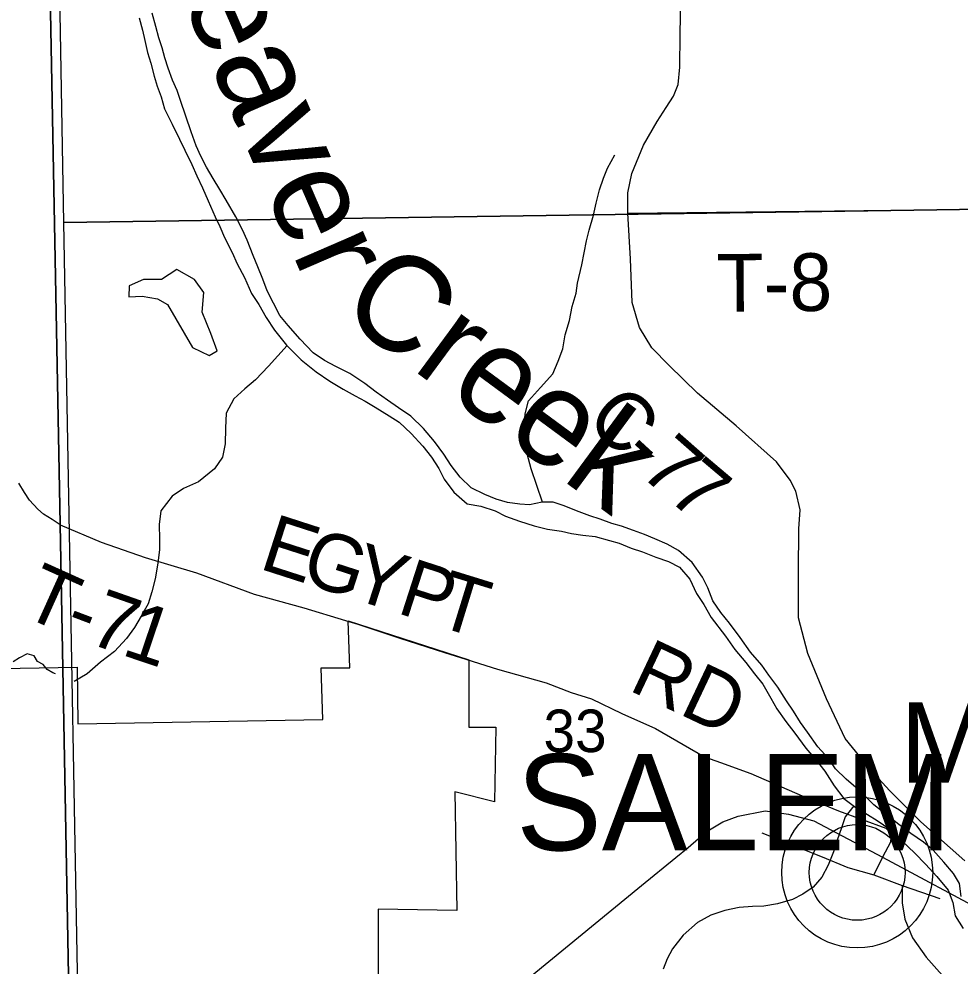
# Model space of a CAD drawing. Extents: x 0 to 34, y 0 to 22.
# Drawn here: x 7.33 to 8.257, y 17.555 to 18.489 of the extents above; entities that cross this region are included whole.
import ezdxf

# ---------------------------------------------------------------- set-up
doc = ezdxf.new("R2010")
doc.units = 0
for name, color, linetype in [('GM_X_Corporation', 7, 'Continuous'), ('GM_X_Corporation_Text', 7, 'Continuous'), ('GM_X_County_Road', 7, 'Continuous'), ('GM_X_County_Road_Text', 7, 'Continuous'), ('GM_X_Minor_Lake', 7, 'Continuous'), ('GM_X_Minor_River', 7, 'Continuous'), ('GM_X_Minor_River_Text', 7, 'Continuous'), ('GM_X_Rail_Line', 7, 'Continuous'), ('GM_X_Section', 7, 'Continuous'), ('GM_X_Section_Text', 7, 'Continuous'), ('GM_X_State_Route', 7, 'Continuous'), ('GM_X_Township', 7, 'Continuous'), ('GM_X_Township_Road', 7, 'Continuous'), ('GM_X_Township_Road_Text', 7, 'Continuous'), ('GM_X_Unincorporated', 7, 'Continuous'), ('GM_X_Unincorporated_Location', 7, 'Continuous'), ('GM_X_Unincorporated_Text', 7, 'Continuous'), ('SH_Cut_Line', 7, 'Continuous')]:
    doc.layers.add(name, color=color, linetype=linetype)

msp = doc.modelspace()

# ---------------------------------------------------------------- linework, layer by layer
at = {"layer": 'GM_X_Corporation'}
msp.add_lwpolyline([(7.08777, 17.84487), (7.38675, 17.85009), (7.38759, 17.79415), (7.62904, 17.79837), (7.62726, 17.84947), (7.65548, 17.84947), (7.65386, 17.89577), (7.77292, 17.85735), (7.77292, 17.79073), (7.79944, 17.79073), (7.79816, 17.71744), (7.75902, 17.72721), (7.76106, 17.61018), (7.68361, 17.61153), (7.68361, 17.42295)], dxfattribs=at)
at = {"layer": 'GM_X_County_Road'}
for points in [[(7.93338, 18.33639), (7.94497, 18.36437), (7.95857, 18.38746), (7.96741, 18.40133), (7.97441, 18.41249), (7.97911, 18.424), (7.98066, 18.44113), (7.98114, 18.47345), (7.98191, 18.52821), (7.982, 18.63427), (7.97887, 18.74901), (7.97794, 18.79423), (7.96834, 18.81722), (7.93809, 18.901), (7.91191, 18.97155), (7.89774, 19.01309), (7.88162, 19.05724), (7.86677, 19.09495), (7.85711, 19.12061), (7.85249, 19.1418), (7.85172, 19.16042), (7.85723, 19.18866), (7.88225, 19.24772), (7.89964, 19.28951)], [(7.92963, 18.29716), (7.92959, 18.31731), (7.93338, 18.33639)], [(8.26146, 17.65929), (8.21808, 17.69755), (8.18739, 17.72847), (8.16951, 17.74786), (8.15818, 17.76208), (8.14375, 17.77965), (8.12545, 17.8188), (8.10704, 17.86328), (8.09756, 17.89843), (8.09777, 17.94405), (8.09804, 17.98625), (8.09918, 18.0049), (8.09499, 18.02344), (8.08944, 18.03435), (8.07614, 18.05232), (8.03625, 18.08762), (7.99831, 18.11991), (7.97037, 18.14708), (7.95327, 18.1646), (7.94107, 18.18449), (7.93371, 18.20943), (7.93207, 18.25235), (7.92963, 18.29716)]]:
    msp.add_lwpolyline(points, dxfattribs=at)
at = {"layer": 'GM_X_Minor_Lake'}
for points in [[(7.50049, 18.16507), (7.51694, 18.15699), (7.52484, 18.16168), (7.51848, 18.17867), (7.51016, 18.1998), (7.51174, 18.2192), (7.50241, 18.23196), (7.48516, 18.24193), (7.47015, 18.2318), (7.4523, 18.23189), (7.43798, 18.22557), (7.43778, 18.21493), (7.45105, 18.21553), (7.46591, 18.21274), (7.47587, 18.20721)], [(7.47587, 18.20721), (7.50049, 18.16507)]]:
    msp.add_lwpolyline(points, dxfattribs=at)
at = {"layer": 'GM_X_Minor_River'}
for points in [[(7.44803, 18.48973), (7.45126, 18.47763), (7.45371, 18.46742), (7.45618, 18.45568), (7.4594, 18.4451), (7.46265, 18.43224), (7.46585, 18.42241), (7.46982, 18.41184), (7.47305, 18.40012), (7.48051, 18.38505), (7.48759, 18.37035), (7.49309, 18.35943), (7.49978, 18.34511), (7.50489, 18.33418), (7.51041, 18.32211), (7.51594, 18.30929), (7.52303, 18.29383), (7.52737, 18.28403), (7.5321, 18.27347), (7.53956, 18.2584), (7.54468, 18.24747), (7.55174, 18.23392), (7.55883, 18.21808), (7.56585, 18.20718), (7.57327, 18.19439), (7.58145, 18.18199), (7.59308, 18.16737), (7.60775, 18.1528), (7.62237, 18.14089), (7.63582, 18.13162), (7.64885, 18.12386), (7.66073, 18.11722), (7.67069, 18.11207), (7.68066, 18.10615), (7.69447, 18.09765), (7.70406, 18.09135), (7.71602, 18.08016), (7.72761, 18.06782), (7.73614, 18.05694), (7.74316, 18.04566), (7.74865, 18.03512), (7.75798, 18.02236), (7.77108, 18.0108), (7.78478, 18.00875), (7.79891, 18.00405), (7.80886, 17.9989), (7.82261, 17.99381), (7.83712, 17.98911), (7.85046, 17.98592), (7.86416, 17.98387), (7.87407, 17.98175), (7.88511, 17.98004), (7.89728, 17.97872), (7.91139, 17.97478), (7.92092, 17.97228), (7.93278, 17.96716), (7.94385, 17.96354), (7.95722, 17.95845), (7.96944, 17.9541), (7.98054, 17.94858), (7.99061, 17.9366), (7.9973, 17.92265), (8.00431, 17.91176), (8.01174, 17.89897), (8.02571, 17.88059), (8.03504, 17.86745), (8.04588, 17.85472), (8.05442, 17.84347), (8.06256, 17.83335), (8.07039, 17.81943), (8.07626, 17.80889), (8.08519, 17.7965), (8.09412, 17.78488), (8.10499, 17.77025), (8.11506, 17.75826), (8.12359, 17.74739), (8.13294, 17.73311), (8.14226, 17.72073), (8.15418, 17.71182), (8.16568, 17.70479), (8.17527, 17.69887), (8.18756, 17.69034), (8.19914, 17.67914), (8.21225, 17.66683), (8.22268, 17.65599), (8.2339, 17.64364), (8.24513, 17.63015), (8.24989, 17.61808), (8.25201, 17.60482), (8.2598, 17.59242)], [(8.25814, 17.62392), (8.25641, 17.6368), (8.25055, 17.64657), (8.24088, 17.65781), (8.23043, 17.66979), (8.22081, 17.6776), (8.20852, 17.68613), (8.1966, 17.69505), (8.18275, 17.70584), (8.17198, 17.71439), (8.15885, 17.72747), (8.1446, 17.73976), (8.13419, 17.74984), (8.12718, 17.75998), (8.11674, 17.77158), (8.10663, 17.78585), (8.09963, 17.7956), (8.09262, 17.8065), (8.086, 17.81665), (8.07742, 17.83018), (8.06849, 17.84218), (8.06149, 17.85194), (8.05027, 17.86467), (8.04016, 17.87931), (8.02968, 17.89319), (8.02115, 17.90368), (8.01337, 17.91532), (8.00822, 17.92815), (8.00311, 17.9387), (7.993, 17.95297), (7.97951, 17.9649), (7.9684, 17.97117), (7.95616, 17.97628), (7.94584, 17.98067), (7.93514, 17.98467), (7.9233, 17.98903), (7.91377, 17.99153), (7.90231, 17.9959), (7.892, 17.99914), (7.87902, 18.00386), (7.86678, 18.00898), (7.85609, 18.0126), (7.84508, 18.01242), (7.8326, 18.00993), (7.8231, 18.01053), (7.81092, 18.01223), (7.79985, 18.01546), (7.78877, 18.02021), (7.77499, 18.02682), (7.76418, 18.03728), (7.75527, 18.04852), (7.74825, 18.0598), (7.73893, 18.07218), (7.72808, 18.08529), (7.71573, 18.09724), (7.70345, 18.10539), (7.69269, 18.11319), (7.68155, 18.12098), (7.6704, 18.12953), (7.65543, 18.13916), (7.64165, 18.14615), (7.63054, 18.15204), (7.6194, 18.15983), (7.60665, 18.17329), (7.59466, 18.18677), (7.58652, 18.19651), (7.57398, 18.22061), (7.56998, 18.23232), (7.56485, 18.24439), (7.56048, 18.25571), (7.55454, 18.27081), (7.54982, 18.28098), (7.54315, 18.29379), (7.53377, 18.30997), (7.52752, 18.3205), (7.52089, 18.3314), (7.51424, 18.34269), (7.50875, 18.35361), (7.50402, 18.36379), (7.49924, 18.37739), (7.48886, 18.40836), (7.48528, 18.41818), (7.48093, 18.42836), (7.47656, 18.44006), (7.47336, 18.45027), (7.47054, 18.4601), (7.46734, 18.46992), (7.46449, 18.48127), (7.46085, 18.4945)], [(7.84546, 18.01242), (7.83429, 18.04528), (7.83025, 18.06003), (7.82895, 18.0695), (7.82802, 18.07974), (7.82785, 18.08999), (7.82845, 18.0995), (7.83166, 18.11246), (7.84359, 18.12558), (7.85551, 18.13907), (7.86101, 18.15131), (7.86536, 18.16354), (7.86779, 18.17726), (7.87211, 18.19138), (7.87453, 18.20547), (7.87849, 18.21846), (7.87985, 18.22835), (7.88411, 18.24628), (7.88657, 18.25809), (7.88865, 18.2699), (7.89151, 18.28058), (7.89582, 18.29547), (7.89828, 18.30728), (7.90148, 18.32025), (7.90547, 18.33171), (7.90948, 18.34165), (7.91686, 18.35469)], [(7.59371, 18.16675), (7.57558, 18.14657), (7.56252, 18.13306), (7.55204, 18.12415), (7.54119, 18.11447), (7.53383, 18.10029), (7.53294, 18.08547), (7.53281, 18.06989), (7.52999, 18.05693), (7.52221, 18.04541), (7.50648, 18.03261), (7.49178, 18.02591), (7.48052, 18.0185), (7.46937, 18.00389), (7.46769, 17.99057), (7.46793, 17.97614), (7.4681, 17.96588), (7.46642, 17.95256), (7.46364, 17.93694), (7.46043, 17.92435), (7.45683, 17.91252), (7.44982, 17.90025), (7.44355, 17.88913), (7.43538, 17.87835), (7.42383, 17.86525), (7.40995, 17.85476), (7.39685, 17.84353), (7.38407, 17.83572)], [(7.36565, 17.84325), (7.36292, 17.84436), (7.35717, 17.84766), (7.35328, 17.85252), (7.34791, 17.85544), (7.34439, 17.86107), (7.33753, 17.8632), (7.33003, 17.85923), (7.32368, 17.85529)], [(8.1521, 17.71337), (8.1437, 17.70253), (8.14008, 17.69183), (8.13573, 17.67961), (8.13212, 17.66815), (8.12703, 17.65478), (8.12077, 17.6429), (8.1122, 17.63326), (8.10206, 17.62625), (8.0919, 17.62115), (8.07716, 17.61672), (8.06353, 17.6146), (8.05253, 17.61403), (8.03926, 17.61305), (8.02526, 17.61016), (8.01128, 17.60575), (7.99812, 17.59832), (7.9839, 17.58593), (7.97349, 17.57246), (7.96834, 17.5625), (7.96433, 17.55256)]]:
    msp.add_lwpolyline(points, dxfattribs=at)
at = {"layer": 'GM_X_Rail_Line'}
msp.add_lwpolyline([(5.51023, 20.26135), (5.52302, 19.27389), (5.52313, 19.26517), (5.54751, 19.26377), (5.61757, 19.25984), (5.64167, 19.25872), (5.7517, 19.25617), (5.84162, 19.25719), (5.92319, 19.25886), (5.97497, 19.26005), (6.13249, 19.26264), (6.14146, 19.26279), (6.18676, 19.26353), (6.21118, 19.26393), (6.3582, 19.26635), (6.84681, 19.27594), (7.27631, 19.27839), (7.34582, 19.27889), (7.37007, 17.99087), (7.38309, 17.29741), (7.46005, 17.29825), (7.4754, 17.30061), (8.28825, 17.30638)], dxfattribs=at)
at = {"layer": 'GM_X_Section'}
for points in [[(7.35625, 19.28264), (8.35915, 19.29722), (8.36978, 18.30261), (7.37374, 18.28816)], [(7.37374, 18.28816), (8.36978, 18.30261), (8.37843, 17.3112), (7.47562, 17.29829), (7.39185, 17.29748)]]:
    msp.add_lwpolyline(points, close=True, dxfattribs=at)
at = {"layer": 'GM_X_State_Route'}
for points in [[(7.97693, 17.66249), (7.989, 17.67237), (8.00662, 17.68786), (8.02318, 17.69763), (8.0383, 17.70319), (8.06484, 17.70856), (8.0877, 17.70512), (8.1129, 17.69869), (8.1806, 17.6629), (8.28719, 17.60563)], [(7.70199, 17.43729), (7.94298, 17.63469), (7.97693, 17.66249)]]:
    msp.add_lwpolyline(points, dxfattribs=at)
at = {"layer": 'GM_X_Township'}
msp.add_lwpolyline([(6.3582, 19.26635), (6.84681, 19.27594), (7.27631, 19.27839), (7.34582, 19.27889), (7.37007, 17.99087), (7.38309, 17.29741), (7.46005, 17.29825), (7.4754, 17.30061), (7.47573, 17.04949), (7.47235, 16.49514), (7.48181, 15.82703), (7.48195, 15.81793), (7.48342, 15.29918)], dxfattribs=at)
at = {"layer": 'GM_X_Township_Road'}
for p, q in [((7.92963, 18.29716), (8.37709, 18.3024)), ((8.1806, 17.6629), (8.17184, 17.64534)), ((8.17184, 17.64534), (8.19991, 17.63498)), ((8.19991, 17.63498), (8.23681, 17.62202))]:
    msp.add_line(p, q, dxfattribs=at)
for points in [[(7.37027, 17.99032), (7.36213, 17.99549), (7.35373, 18.00067), (7.34797, 18.0055), (7.33988, 18.01448), (7.33485, 18.02198), (7.32941, 18.03136)], [(7.37027, 17.99032), (7.41048, 17.9733), (7.45376, 17.95805), (7.50463, 17.94294), (7.56132, 17.92183), (7.61027, 17.90858), (7.65132, 17.89606)], [(7.65132, 17.89606), (7.66345, 17.89236), (7.70479, 17.8786), (7.74881, 17.86451), (7.76472, 17.85947)], [(7.76472, 17.85947), (7.80123, 17.8479), (7.84903, 17.83463), (7.87356, 17.82515), (7.89384, 17.81865), (7.92377, 17.80432), (7.95676, 17.78966), (8.00498, 17.76176), (8.02081, 17.756)], [(8.02081, 17.756), (8.0506, 17.74516), (8.10138, 17.72326), (8.13704, 17.70827), (8.18385, 17.6912), (8.1879, 17.68703), (8.18882, 17.6824), (8.18828, 17.67747), (8.1806, 17.6629)], [(8.06172, 17.68665), (8.12095, 17.66294), (8.14622, 17.65261), (8.17184, 17.64534)], [(8.19991, 17.63498), (8.19986, 17.61769), (8.20241, 17.60176), (8.20996, 17.58325), (8.22361, 17.56409), (8.2368, 17.54948), (8.25425, 17.53), (8.26717, 17.5093), (8.27772, 17.48739), (8.28037, 17.4715), (8.28456, 17.44913), (8.28865, 17.40966), (8.28845, 17.30583)]]:
    msp.add_lwpolyline(points, dxfattribs=at)
at = {"layer": 'GM_X_Unincorporated'}
for radius in [0.0744, 0.04716]:
    msp.add_circle((8.15552, 17.64773), radius, dxfattribs=at)
at = {"layer": 'GM_X_Unincorporated_Location'}
msp.add_line((8.15552, 17.64773), (8.15552, 17.64773), dxfattribs=at)
at = {"layer": 'SH_Cut_Line'}
for points in [[(6.3582, 19.26635), (6.84681, 19.27594), (7.27631, 19.27839), (7.34582, 19.27889), (7.37007, 17.99087), (7.38309, 17.29741), (7.46005, 17.29825), (7.4754, 17.30061), (8.28825, 17.30638)], [(8.28825, 17.30638), (7.4754, 17.30061), (7.46005, 17.29825), (7.38309, 17.29741), (7.37007, 17.99087), (7.34582, 19.27889), (7.27631, 19.27839), (6.84681, 19.27594), (6.3582, 19.26635)]]:
    msp.add_lwpolyline(points, dxfattribs=at)

# ---------------------------------------------------------------- texts
at = {"layer": 'GM_X_Corporation_Text'}
msp.add_text('SALEM', height=0.094697, rotation=0.00001, dxfattribs=at).set_placement((7.81947, 17.66959))
at = {"layer": 'GM_X_County_Road_Text'}
for s, rotation, p in [('C', 314.93239, (7.88635, 18.09257)), ('7', 318.69687, (7.93946, 18.04094)), ('-', 317.38611, (7.92123, 18.05769)), ('7', 319.82447, (7.96668, 18.01705))]:
    msp.add_text(s, height=0.05682, rotation=rotation, dxfattribs=at).set_placement(p)
at = {"layer": 'GM_X_Minor_River_Text'}
for s, height, rotation, p in [('Beaver', 0.09473, 293.39755, (7.45574, 18.58827)), ('Creek', 0.094724, 323.61503, (7.64187, 18.19861))]:
    msp.add_text(s, height=height, rotation=rotation, dxfattribs=at).set_placement(p)
at = {"layer": 'GM_X_Section_Text'}
msp.add_text('33', height=0.041856, rotation=0.00001, dxfattribs=at).set_placement((7.84638, 17.76631))
at = {"layer": 'GM_X_Township_Road_Text'}
for s, height, rotation, p in [('T-8', 0.056818, 0.4772, (8.0172, 18.20014)), ('E', 0.05682, 342.12137, (7.56488, 17.94754)), ('G', 0.05682, 342.12203, (7.60533, 17.93449)), ('Y', 0.05682, 342.1203, (7.65291, 17.91914)), ('P', 0.05682, 342.14908, (7.70052, 17.90378)), ('T', 0.05682, 335.73552, (7.32998, 17.90214)), ('T', 0.05682, 342.84276, (7.73773, 17.89181)), ('7', 0.05682, 340.67079, (7.39551, 17.87446)), ('1', 0.05682, 341.33347, (7.42921, 17.86264)), ('-', 0.05682, 339.33158, (7.37231, 17.88319)), ('RD', 0.056818, 334.74838, (7.92888, 17.8279))]:
    msp.add_text(s, height=height, rotation=rotation, dxfattribs=at).set_placement(p)
at = {"layer": 'GM_X_Unincorporated_Text'}
msp.add_text('Millville', height=0.078977, rotation=0.00001, dxfattribs=at).set_placement((8.19805, 17.73621))

doc.saveas('drawing.dxf')
